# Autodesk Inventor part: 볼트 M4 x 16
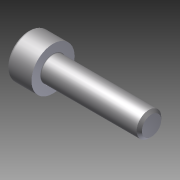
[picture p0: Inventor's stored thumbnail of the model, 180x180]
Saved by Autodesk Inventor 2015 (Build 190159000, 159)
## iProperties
Created: 2025-08
Part Number: 볼트 M4 x 16
Material: 일반
Document SubType Name: Modeling
Designer: USER
Density: 1 g/cm^3
Appearance: 기본값
Author: USER
Author: jhkim
Description: 6각 소켓 머리 캡 나사
Creation Date: 2025-08-05
Sending System: Autodesk Inventor 2026
Preprocessor: ST-DEVELOPER v20.1
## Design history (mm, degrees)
node "볼트 M4 x 161"
body "Solid1"
node "기준1"
